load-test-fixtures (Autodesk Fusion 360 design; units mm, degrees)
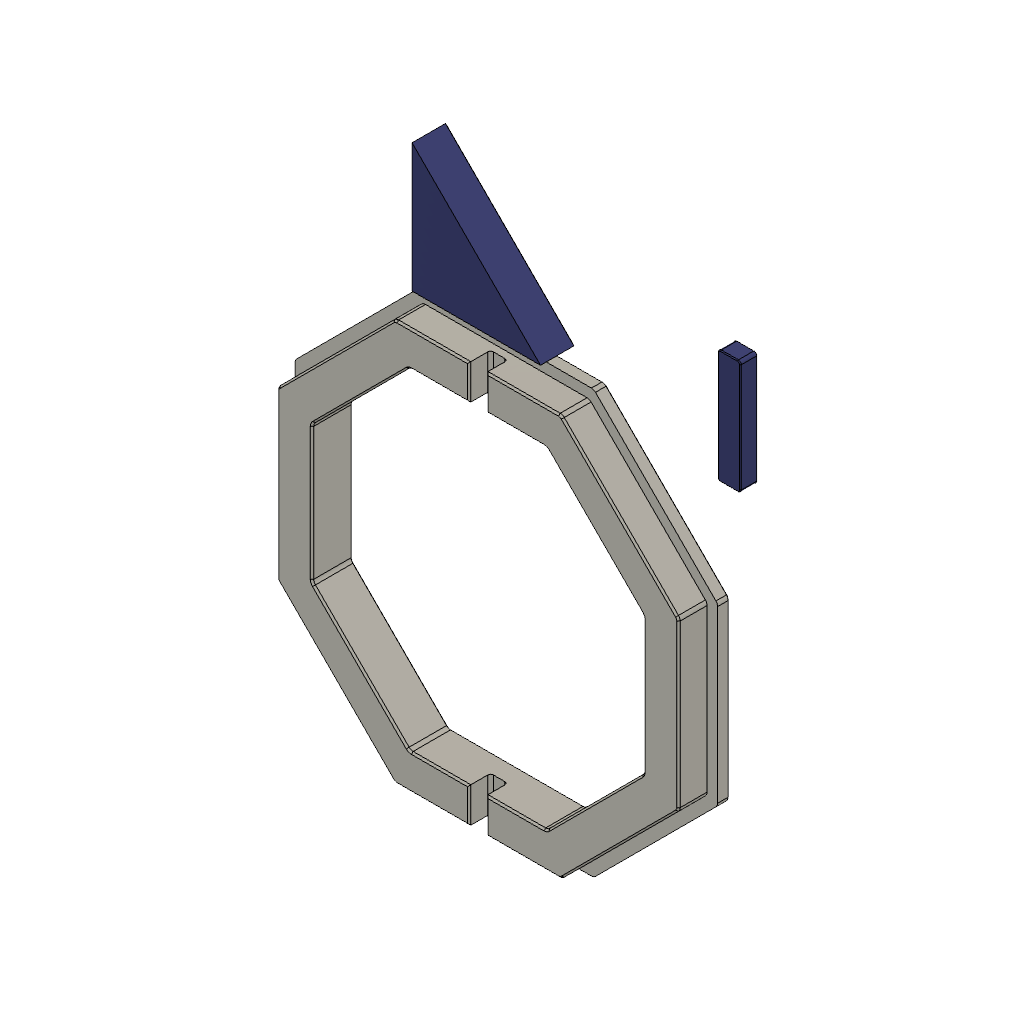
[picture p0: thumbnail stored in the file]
part number: 2026-11-02-20-20-52-868
part number: 2026-11-02-20-20-53-079
part number: 2026-11-02-20-20-56-953
part number: 2026-11-02-20-20-59-335
parameter "fixtureBedRelief" = 0.3 comment "Bed-contact edge relief; do not scale to change fits."
parameter "fixtureEntryChamfer" = 0.3 comment "Small clearance-hole lead-in."
parameter "fixtureBackerLip" = 148 comment "Recessed from the 150 mm integrated housing; the jaws contact the end rim."
parameter "fixtureBackerLipThickness" = 4 comment "End stop; the clamp should grip the housing end band."
parameter "fixtureBackerPilot" = 140.6 comment "Trial slip fit in the nominal 141 mm integrated end-rim opening."
parameter "fixtureBackerDepth" = 10 comment "Extends from end X130 to X120, matching the solid end rim."
parameter "fixtureBackerOpening" = 116 comment "Open center for access and lower material use."
parameter "fixtureBackerHeight" = 14 (= "fixtureBackerLipThickness + fixtureBackerDepth") comment "Total backer height in print orientation."
parameter "fixtureBackerPilotRadius" = 2 comment "Male corner relief; verify against actual integrated-rim corner geometry."
parameter "fixtureBackerCornerRadius" = 2 comment "Lip and inner opening corner radii."
parameter "fixtureBackerEntry" = 0.6 comment "Pilot entry lead-in."
parameter "fixtureCordSlotWidth" = 6 comment "Clearance for cord passing through the housing load ports."
parameter "fixtureCordSlotFloor" = 6.5 comment "Port center is at local Z9; slot remains open through the pilot tip."
parameter "fixtureCordSlotHeight" = 8.5 (= "fixtureBackerHeight - fixtureCordSlotFloor + 1 mm") comment "Open-ended slot extends past the pilot tip."
parameter "fixtureCordSlotCenter" = 10.75 (= "( fixtureBackerHeight + 1 mm + fixtureCordSlotFloor ) / 2") comment "Height of the slot sketch center."
parameter "fixtureCordSlotRadius" = 1 comment "Round the closed slot corners."
parameter "fixtureShoeLength" = 8 comment "Along body X; contact region X121..129 stays inside the solid end rim."
parameter "fixtureShoeWidth" = 40 comment "Across the 62.13 mm outer facet, with clearance from the corner rails."
parameter "fixtureShoeThickness" = 6 comment "Flat load-spreading shoe; add thin grippy lining if the vise needs it."
parameter "fixtureSetupLeg" = 45 comment "Equal legs establish a 45 degree reference face."
parameter "fixtureSetupWidth" = 12 comment "Print the triangular face on the bed."
sketch "Octagonal backer lip" plane through (0, 0, 0) normal (0, 0, 1) x axis (1, 0, 0)
  line L1 (30.6518, 74) -> (74, 30.6518)
  line L2 (-30.6518, 74) -> (30.6518, 74)
  line L3 (-74, 30.6518) -> (-30.6518, 74)
  line L4 (-74, -30.6518) -> (-74, 30.6518)
  line L5 (-30.6518, -74) -> (-74, -30.6518)
  line L6 (30.6518, -74) -> (-30.6518, -74)
  line L7 (74, -30.6518) -> (30.6518, -74)
  line L8 (74, 30.6518) -> (74, -30.6518)
  point P1 (0, 0)
  point P10 (0, 0)
  point P3 (30.6518, 74)
  point P8 (30.6518, -74)
  coincident P1 P10
  horizontal L2
  dimension "d22" distance P3 P8 = 148 (= "fixtureBackerLip")
extrude "Extrude1" new body sketch "Octagonal backer lip" along normal blind 4 (= "fixtureBackerLipThickness")
fillet "Fillet1" radius 2 (= "fixtureBackerCornerRadius")
work_plane "WorkPlane1" AlongDistance 4 (= "fixtureBackerLipThickness") ExtraOffset 0
sketch "140.6 mm octagonal end-rim pilot" plane through (0, 0, 4) normal (0, 0, 1) x axis (1, 0, 0)
  line L1 (29.1192, 70.3) -> (70.3, 29.1192)
  line L2 (-29.1192, 70.3) -> (29.1192, 70.3)
  line L3 (-70.3, 29.1192) -> (-29.1192, 70.3)
  line L4 (-70.3, -29.1192) -> (-70.3, 29.1192)
  line L5 (-29.1192, -70.3) -> (-70.3, -29.1192)
  line L6 (29.1192, -70.3) -> (-29.1192, -70.3)
  line L7 (70.3, -29.1192) -> (29.1192, -70.3)
  line L8 (70.3, 29.1192) -> (70.3, -29.1192)
  point P1 (0, 0)
  point P10 (0, 0)
  point P3 (29.1192, 70.3)
  point P8 (29.1192, -70.3)
  coincident P1 P10
  horizontal L2
  dimension "d29" distance P3 P8 = 140.6 (= "fixtureBackerPilot")
extrude "Extrude2" add sketch "140.6 mm octagonal end-rim pilot" along normal blind 10 (= "fixtureBackerDepth")
fillet "Fillet2" radius 2 (= "fixtureBackerPilotRadius")
sketch "Octagonal backer opening" plane through (0, 0, 0) normal (0, 0, 1) x axis (1, 0, 0)
  line L1 (24.0244, 58) -> (58, 24.0244)
  line L2 (-24.0244, 58) -> (24.0244, 58)
  line L3 (-58, 24.0244) -> (-24.0244, 58)
  line L4 (-58, -24.0244) -> (-58, 24.0244)
  line L5 (-24.0244, -58) -> (-58, -24.0244)
  line L6 (24.0244, -58) -> (-24.0244, -58)
  line L7 (58, -24.0244) -> (24.0244, -58)
  line L8 (58, 24.0244) -> (58, -24.0244)
  point P1 (0, 0)
  point P10 (0, 0)
  point P3 (24.0244, 58)
  point P8 (24.0244, -58)
  coincident P1 P10
  horizontal L2
  dimension "d34" distance P3 P8 = 116 (= "fixtureBackerOpening")
extrude "Extrude3" cut sketch "Octagonal backer opening" along normal blind 14 (= "fixtureBackerHeight")
fillet "Fillet3" radius 2 (= "fixtureBackerCornerRadius")
sketch "Open cord slots" plane through (0, 0, 0) normal (0, 1, 0) x axis (1, 0, 0)
  line L1 (0, -10.75) -> (0, 0)
  line L2 (3, -15) -> (-3, -15)
  line L3 (3, -6.5) -> (3, -15)
  line L4 (-3, -6.5) -> (3, -6.5)
  line L5 (-3, -15) -> (-3, -6.5)
  line L6 (3, -6.5) -> (-3, -15)
  point P2 (0, -10.75)
  point P1 (0, 0)
  point P3 (-3, -15)
  point P4 (3, -15)
  point P5 (3, -6.5)
  vertical L1
  horizontal L2
  vertical L3
  horizontal L4
  vertical L5
  midpoint P2 L6
  dimension "d39" distance P1 P2 = 10.75 (= "fixtureCordSlotCenter")
  dimension "d40" distance P3 P4 = 6 (= "fixtureCordSlotWidth")
  dimension "d41" distance P4 P5 = 8.5 (= "fixtureCordSlotHeight")
extrude "Extrude4" cut sketch "Open cord slots" profile of L2 L3 L4 L5 distance 142.6 (= "fixtureBackerPilot + 2 mm")
fillet "Fillet4" radius 1 (= "fixtureCordSlotRadius")
chamfer "Chamfer1" distance 0.3 (= "fixtureBedRelief")
chamfer "Chamfer2" distance 0.6 (= "fixtureBackerEntry")
sketch "Equal-leg setup triangle" plane through (0, 0, 0) normal (0, 0, 1) x axis (1, 0, 0)
  line L1 (45, 0) -> (0, 0)
  line L2 (0, 45) -> (45, 0)
  line L3 (0, 0) -> (0, 45)
  point P1 (0, 0)
  point P2 (45, 0)
  horizontal L1
  vertical L3
  equal L1 L3
  dimension "d48" distance P1 P2 = 45 (= "fixtureSetupLeg")
extrude "Extrude1" new body sketch "Equal-leg setup triangle" along normal blind 12 (= "fixtureSetupWidth") bodies "45 degree setup block print"
chamfer "Chamfer1" distance 0.3 (= "fixtureBedRelief")
sketch "Clamp shoe footprint" plane through (0, 0, 0) normal (0, 0, 1) x axis (1, 0, 0)
  line L1 (4, -20) -> (-4, -20)
  line L2 (4, 20) -> (4, -20)
  line L3 (-4, 20) -> (4, 20)
  line L4 (-4, -20) -> (-4, 20)
  line L5 (4, 20) -> (-4, -20)
  point P1 (0, 0)
  point P2 (-4, -20)
  point P3 (4, -20)
  point P4 (4, 20)
  horizontal L1
  vertical L2
  horizontal L3
  vertical L4
  midpoint P1 L5
  dimension "d52" distance P2 P3 = 8 (= "fixtureShoeLength")
  dimension "d53" distance P3 P4 = 40 (= "fixtureShoeWidth")
extrude "Extrude1" new body sketch "Clamp shoe footprint" profile of L1 L2 L3 L4 along normal blind 6 (= "fixtureShoeThickness") bodies "Flat clamp shoe print two"
fillet "Fillet1" radius 1
chamfer "Chamfer1" distance 0.3 (= "fixtureBedRelief")
chamfer "Chamfer2" distance 0.3 (= "fixtureEntryChamfer")
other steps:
create_component "CreateComponent1"
create_component "CreateComponent2"
create_component "CreateComponent3"
named bodies: "Housing end backer print two", "45 degree setup block print", "Flat clamp shoe print two"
